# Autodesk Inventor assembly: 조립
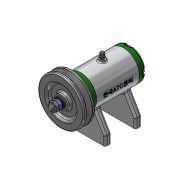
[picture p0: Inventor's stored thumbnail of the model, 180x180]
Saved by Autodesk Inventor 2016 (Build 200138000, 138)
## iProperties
Created: 2018-05
Part Number: 조립
Material: 일반
Document SubType Name: Assembly
Designer: Administrator
Author: Administrator
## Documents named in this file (16)
- C:\Users\Administrator\Desktop\480507V1009\답안조립품.iam
- C:\Users\Administrator\Desktop\480507V1009\본체.ipt
- C:\Users\Administrator\Desktop\480507V1009\축.ipt
- C:\Users\Administrator\Desktop\480507V1009\키 3x3x12.ipt
- C:\Users\Administrator\Desktop\480507V1009\베어링 6002.ipt
- C:\Users\Administrator\Desktop\480507V1009\뒤커버.ipt
- C:\Users\Administrator\Desktop\480507V1009\앞커버.ipt
- C:\Users\Administrator\Desktop\480507V1009\오일 실 15 25 7.ipt
- C:\Users\Administrator\Desktop\480507V1009\볼트 M4x12.ipt
- C:\Users\Administrator\Desktop\480507V1009\볼트 M6x8.ipt
- C:\Users\Administrator\Desktop\480507V1009\와셔 6x11.5.ipt
- C:\Users\Administrator\Desktop\480507V1009\니플 M6x0.75.ipt
- C:\Users\Administrator\Desktop\480507V1009\V벨트풀리.ipt
- C:\Users\Administrator\Desktop\480507V1009\너트 M8.ipt
- C:\Users\Administrator\Desktop\480507V1009\스프링와셔 8.ipt
- C:\Users\Administrator\Desktop\480507V1009\와셔 8x17.ipt
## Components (1 placed, 1 different names)
1. V벨트풀리:1 — 각도:2
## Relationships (1: Angle 1)
- 각도:2 [Angle]: V벨트풀리:1
